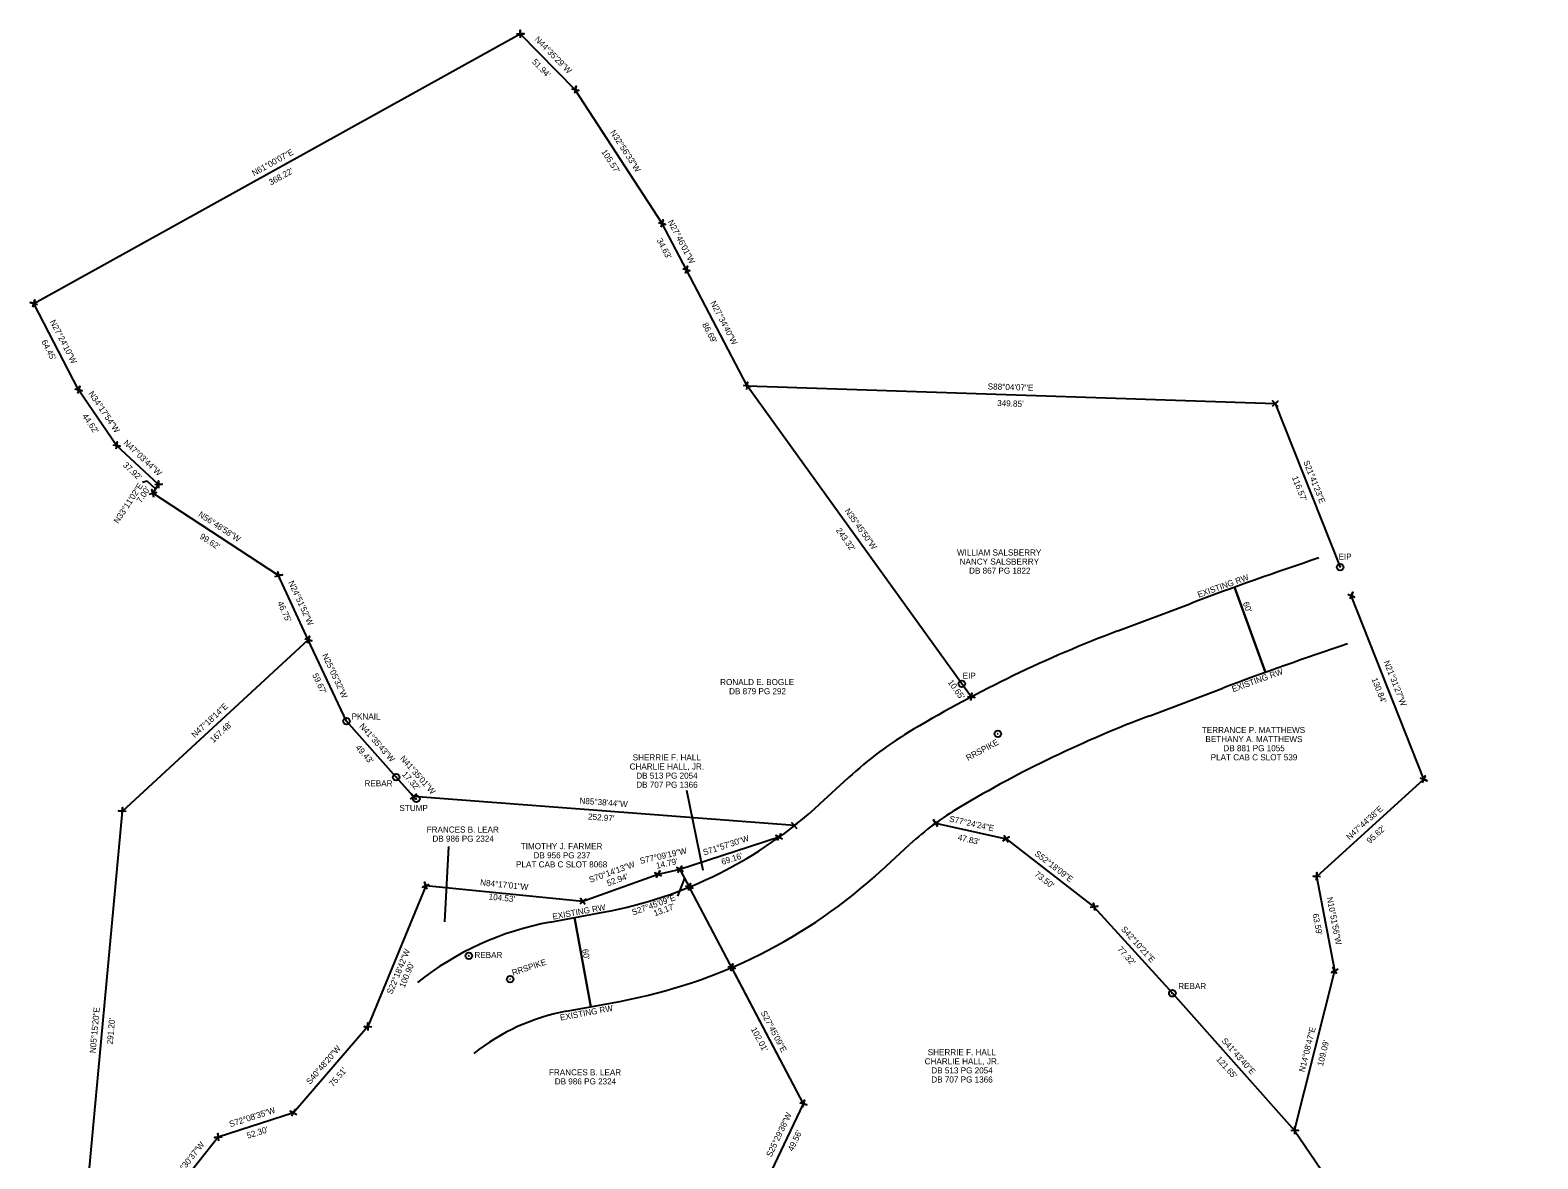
# Model space of a CAD drawing. Extents: x 860808 to 861835, y 630123 to 631311.
# Drawn here: x 860808 to 861806, y 630563 to 631311 of the extents above; entities that cross this region are included whole.
import ezdxf

# ---------------------------------------------------------------- set-up
doc = ezdxf.new("R2010")
doc.units = 0
for name, color, linetype in [('Exist Property Corner CELL', 7, 'Continuous'), ('Exist Property Iron Pin CELL', 7, 'Continuous'), ('Exist Property Line', 7, 'Continuous'), ('Exist Property Text', 7, 'Continuous'), ('Exist Right of Way Line', 7, 'Continuous'), ('Exist Right of Way Text', 7, 'Continuous')]:
    doc.layers.add(name, color=color, linetype=linetype)

msp = doc.modelspace()

# ---------------------------------------------------------------- linework, layer by layer
at = {"layer": 'Exist Property Corner CELL'}
for p, q in [((861132.38, 631308.34), (861132.38, 631308.34)), ((861168.84, 631271.35), (861168.84, 631271.35)), ((861226.25, 631182.75), (861226.25, 631182.75)), ((861242.38, 631152.11), (861242.38, 631152.11)), ((860810.32, 631129.83), (860810.32, 631129.83)), ((860839.98, 631072.61), (860839.98, 631072.61)), ((861282.52, 631075.27), (861282.52, 631075.27)), ((861632.17, 631063.48), (861632.17, 631063.48)), ((860865.13, 631035.75), (860865.13, 631035.75)), ((860889.06, 631004.06), (860889.06, 631004.06)), ((860892.89, 631009.92), (860892.89, 631009.92)), ((860972.43, 630949.54), (860972.43, 630949.54)), ((861682.54, 630936.37), (861682.54, 630936.37)), ((860992.09, 630907.12), (860992.09, 630907.12)), ((861430.95, 630869.19), (861430.95, 630869.19)), ((861730.55, 630814.66), (861730.55, 630814.66)), ((861061.7, 630803.16), (861061.7, 630803.16)), ((860869, 630793.55), (860869, 630793.55)), ((861313.94, 630783.95), (861313.94, 630783.95)), ((861407.39, 630785.59), (861407.39, 630785.59)), ((861303.9, 630776.38), (861303.9, 630776.38)), ((861454.06, 630775.16), (861454.06, 630775.16)), ((861223.71, 630751.67), (861223.71, 630751.67)), ((861238.13, 630754.96), (861238.13, 630754.96)), ((861069.88, 630744.18), (861069.88, 630744.18)), ((861244.27, 630743.31), (861244.27, 630743.31)), ((861659.77, 630750.36), (861659.77, 630750.36)), ((861173.89, 630733.77), (861173.89, 630733.77)), ((861512.22, 630730.22), (861512.22, 630730.22)), ((861272.31, 630690.01), (861272.31, 630690.01)), ((861671.76, 630687.91), (861671.76, 630687.91)), ((861031.58, 630650.84), (861031.58, 630650.84)), ((860982.23, 630593.68), (860982.23, 630593.68)), ((861319.81, 630599.73), (861319.81, 630599.73)), ((861645.1, 630582.13), (861645.1, 630582.13)), ((860932.45, 630577.65), (860932.45, 630577.65))]:
    msp.add_line(p, q, dxfattribs=at)
for points in [[(861129.88, 631308.36), (861134.88, 631308.32), (861132.38, 631308.34), (861132.4, 631310.84), (861132.36, 631305.84)], [(861166.4, 631271.87), (861171.29, 631270.83), (861168.84, 631271.35), (861169.37, 631273.79), (861168.32, 631268.91)], [(861223.86, 631183.5), (861228.64, 631182.01), (861226.25, 631182.75), (861226.99, 631185.14), (861225.51, 631180.37)], [(861240, 631152.86), (861244.77, 631151.36), (861242.38, 631152.11), (861243.13, 631154.5), (861241.64, 631149.73)], [(860809.63, 631127.43), (860811.01, 631132.24), (860810.32, 631129.83), (860807.92, 631130.52), (860812.72, 631129.14)], [(860837.6, 631073.37), (860842.37, 631071.86), (860839.98, 631072.61), (860840.74, 631075), (860839.23, 631070.23)], [(861280.05, 631075.67), (861284.99, 631074.87), (861282.52, 631075.27), (861282.92, 631077.74), (861282.12, 631072.8)], [(861630.34, 631061.77), (861634, 631065.19), (861632.17, 631063.48), (861630.46, 631065.31), (861633.88, 631061.65)], [(860862.67, 631036.22), (860867.58, 631035.29), (860865.13, 631035.75), (860865.59, 631038.21), (860864.66, 631033.3)], [(860890.39, 631009.83), (860895.39, 631010.01), (860892.89, 631009.92), (860892.8, 631012.42), (860892.98, 631007.42)], [(860886.61, 631003.55), (860891.5, 631004.57), (860889.06, 631004.06), (860888.54, 631006.51), (860889.57, 631001.62)], [(860969.98, 630949.03), (860974.88, 630950.05), (860972.43, 630949.54), (860971.92, 630951.99), (860972.94, 630947.09)], [(861680.25, 630937.37), (861684.83, 630935.38), (861682.54, 630936.37), (861683.54, 630938.66), (861681.55, 630934.08)], [(860989.74, 630907.97), (860994.44, 630906.27), (860992.09, 630907.12), (860992.94, 630909.47), (860991.24, 630904.77)], [(861428.48, 630869.59), (861433.42, 630868.79), (861430.95, 630869.19), (861431.35, 630871.66), (861430.55, 630866.72)], [(861728.25, 630815.65), (861732.84, 630813.66), (861730.55, 630814.66), (861731.54, 630816.95), (861729.55, 630812.36)], [(861059.81, 630801.53), (861063.6, 630804.79), (861061.7, 630803.16), (861060.07, 630805.06), (861063.33, 630801.26)], [(860868.89, 630791.05), (860869.1, 630796.05), (860869, 630793.55), (860866.5, 630793.65), (860871.49, 630793.45)], [(861312.04, 630782.33), (861315.84, 630785.58), (861313.94, 630783.95), (861312.31, 630785.85), (861315.57, 630782.06)], [(861405.28, 630784.25), (861409.5, 630786.93), (861407.39, 630785.59), (861406.05, 630787.7), (861408.73, 630783.48)], [(861302.76, 630774.15), (861305.03, 630778.61), (861303.9, 630776.38), (861301.67, 630777.52), (861306.12, 630775.25)], [(861451.95, 630773.82), (861456.18, 630776.5), (861454.06, 630775.16), (861452.73, 630777.27), (861455.4, 630773.05)], [(861222.65, 630749.41), (861224.78, 630753.93), (861223.71, 630751.67), (861221.45, 630752.74), (861225.98, 630750.61)], [(861236.8, 630752.85), (861239.47, 630757.08), (861238.13, 630754.96), (861236.02, 630756.29), (861240.25, 630753.63)], [(861659.65, 630747.86), (861659.89, 630752.85), (861659.77, 630750.36), (861657.28, 630750.48), (861662.27, 630750.24)], [(861070.85, 630741.88), (861068.92, 630746.49), (861069.88, 630744.18), (861067.58, 630743.22), (861072.19, 630745.15)], [(861241.88, 630744.05), (861246.65, 630742.57), (861244.27, 630743.31), (861245.01, 630745.7), (861243.52, 630740.92)], [(861171.96, 630732.19), (861175.83, 630735.35), (861173.89, 630733.77), (861172.31, 630735.71), (861175.48, 630731.84)], [(861509.74, 630729.9), (861514.7, 630730.53), (861512.22, 630730.22), (861511.9, 630732.7), (861512.54, 630727.74)], [(861269.92, 630690.75), (861274.7, 630689.27), (861272.31, 630690.01), (861273.05, 630692.4), (861271.57, 630687.62)], [(861673.04, 630685.76), (861670.48, 630690.05), (861671.76, 630687.91), (861669.61, 630686.63), (861673.91, 630689.19)], [(861031.76, 630648.35), (861031.4, 630653.33), (861031.58, 630650.84), (861029.08, 630650.66), (861034.07, 630651.02)], [(861317.43, 630600.48), (861322.2, 630598.99), (861319.81, 630599.73), (861320.56, 630602.12), (861319.07, 630597.35)], [(860981.09, 630591.46), (860983.37, 630595.91), (860982.23, 630593.68), (860980.01, 630594.83), (860984.46, 630592.54)], [(861642.6, 630582.27), (861647.59, 630581.98), (861645.1, 630582.13), (861645.24, 630584.62), (861644.95, 630579.63)], [(860932.73, 630575.16), (860932.17, 630580.13), (860932.45, 630577.65), (860929.97, 630577.37), (860934.94, 630577.93)]]:
    msp.add_lwpolyline(points, dxfattribs=at)
at = {"layer": 'Exist Property Iron Pin CELL'}
for centre, radius in [((861675.25, 630955.16), 2.2), ((861675.25, 630955.16), 0.0707), ((861424.73, 630877.83), 2.2), ((861424.73, 630877.83), 0.0707), ((861017.39, 630853.08), 2.2), ((861017.39, 630853.08), 0.0707), ((861448.54, 630844.78), 2.2), ((861448.54, 630844.78), 0.0707), ((861050.21, 630816.12), 2.2), ((861050.21, 630816.12), 0.0707), ((861063.62, 630801.67), 2.2), ((861063.62, 630801.67), 0.0707), ((861098.31, 630697.67), 2.2), ((861098.31, 630697.67), 0.0707), ((861125.7, 630682.29), 2.2), ((861125.7, 630682.29), 0.0707), ((861564.13, 630672.91), 2.2), ((861564.13, 630672.91), 0.0707)]:
    msp.add_circle(centre, radius, dxfattribs=at)
at = {"layer": 'Exist Property Line'}
for p, q in [((860810.32, 631129.83), (861132.38, 631308.34)), ((861168.84, 631271.35), (861132.38, 631308.34)), ((861226.25, 631182.75), (861168.84, 631271.35)), ((861242.38, 631152.11), (861226.25, 631182.75)), ((861282.52, 631075.27), (861242.38, 631152.11)), ((860839.98, 631072.61), (860810.32, 631129.83)), ((860865.13, 631035.75), (860839.98, 631072.61)), ((861424.73, 630877.83), (861282.52, 631075.27)), ((861282.52, 631075.27), (861632.17, 631063.48)), ((861632.17, 631063.48), (861675.25, 630955.16)), ((860892.89, 631009.92), (860865.13, 631035.75)), ((860889.06, 631004.06), (860892.89, 631009.92)), ((860972.43, 630949.54), (860889.06, 631004.06)), ((860992.09, 630907.12), (860972.43, 630949.54)), ((861730.55, 630814.66), (861682.54, 630936.37)), ((860869, 630793.55), (860992.09, 630907.12)), ((861017.39, 630853.08), (860992.09, 630907.12)), ((861430.95, 630869.19), (861424.73, 630877.83)), ((861050.21, 630816.12), (861017.39, 630853.08)), ((861061.7, 630803.16), (861050.21, 630816.12)), ((861659.77, 630750.36), (861730.55, 630814.66)), ((861313.94, 630783.95), (861061.7, 630803.16)), ((860842.32, 630503.57), (860869, 630793.55)), ((861407.39, 630785.59), (861454.06, 630775.16)), ((861303.9, 630776.38), (861238.13, 630754.96)), ((861454.06, 630775.16), (861512.22, 630730.22)), ((861223.71, 630751.67), (861173.89, 630733.77)), ((861238.13, 630754.96), (861223.71, 630751.67)), ((861238.13, 630754.96), (861319.81, 630599.73)), ((861238.13, 630754.96), (861244.27, 630743.31)), ((861238.13, 630754.96), (861319.81, 630599.73)), ((861069.88, 630744.18), (861031.58, 630650.84)), ((861173.89, 630733.77), (861069.88, 630744.18)), ((861671.76, 630687.91), (861659.77, 630750.36)), ((861512.22, 630730.22), (861564.13, 630672.91)), ((861272.31, 630690.01), (861319.81, 630599.73)), ((861645.1, 630582.13), (861671.76, 630687.91)), ((861564.13, 630672.91), (861645.1, 630582.13)), ((861031.58, 630650.84), (860982.23, 630593.68)), ((860982.23, 630593.68), (860932.45, 630577.65)), ((861319.81, 630599.73), (861298.48, 630555)), ((861645.1, 630582.13), (861806.12, 630345.46)), ((860932.45, 630577.65), (860901.8, 630539.13))]:
    msp.add_line(p, q, dxfattribs=at)
at = {"layer": 'Exist Property Text'}
for p, q in [((861253.6, 630754.21), (861242.69, 630807.16)), ((861082.44, 630720.21), (861085.18, 630770.07)), ((861241.2, 630749.14), (861236.48, 630737.31))]:
    msp.add_line(p, q, dxfattribs=at)
msp.add_lwpolyline([(860890.97, 631006.99), (860885.3, 631012.12), (860882.36, 631011.26)], dxfattribs=at)
at = {"layer": 'Exist Right of Way Line'}
for p, q in [((861528.04, 630912.91), (861576.28, 630931.11)), ((861549.22, 630856.77), (861597.46, 630874.98)), ((861330.82, 630798.34), (861349.56, 630815.59)), ((861371.46, 630754.2), (861390.19, 630771.45)), ((861152.14, 630720.03), (861187.36, 630726.57)), ((861163.1, 630661.04), (861198.32, 630667.58))]:
    msp.add_line(p, q, dxfattribs=at)
for centre, radius, start, end in [((862382.98, 628793.25), 2285, 108.41329, 110.67352), ((861829.89, 630112.97), 855, 110.67352, 120.7515), ((862382.98, 628793.25), 2225, 108.41329, 110.67352), ((861829.89, 630112.97), 795, 110.67352, 120.7515), ((861525.65, 630624.3), 260, 120.7515, 132.63313), ((861134.4, 631011.69), 290, 280.52274, 312.63313), ((861525.65, 630624.3), 200, 120.7515, 132.63313), ((861134.4, 631011.69), 350, 280.52274, 312.63313), ((861188.67, 630523.39), 200, 100.52274, 128.42782), ((861188.67, 630523.39), 140, 100.52274, 128.42782)]:
    msp.add_arc(centre, radius, start, end, dxfattribs=at)
at = {"layer": 'Exist Right of Way Text'}
for p, q in [((861625.71, 630885.42), (861605.29, 630941.84)), ((861605.29, 630941.84), (861625.71, 630885.42)), ((861179.18, 630664.02), (861168.22, 630723.01)), ((861168.22, 630723.01), (861179.18, 630664.02))]:
    msp.add_line(p, q, dxfattribs=at)

# ---------------------------------------------------------------- texts
at = {"layer": 'Exist Property Text'}
for s, rotation, p in [('N44°35\'29"W', 314.59135, (861141.6, 631304.37)), ("51.94'", 314.59135, (861139.87, 631289.46)), ('N32°56\'33"W', 302.94247, (861191.65, 631243.1)), ('N61°00\'07"E', 28.99802, (860956.1, 631214.06)), ("105.57'", 302.94247, (861185.89, 631230.26)), ("368.22'", 28.99802, (860967.27, 631207.9)), ('N27°46\'01"W', 297.76691, (861229.9, 631183.94)), ("34.63'", 297.76691, (861222.6, 631171.66)), ('N27°34\'40"W', 297.57774, (861258.08, 631130.22)), ('N27°24\'10"W', 297.40274, (860820.83, 631117.76)), ("86.69'", 297.57774, (861252.67, 631115.87)), ("64.45'", 297.40274, (860815.19, 631104.52)), ('N34°17\'54"W', 304.2983, (860846.28, 631070.08)), ('S88°04\'07"E', 358.06854, (861441.83, 631072.9)), ("349.85'", 358.06854, (861448.1, 631061.88)), ("44.62'", 304.2983, (860842.15, 631055.18)), ('N47°03\'44"W', 317.06219, (860869.38, 631036.96)), ("37.92'", 317.06219, (860869, 631022.29)), ('S21°41\'23"E', 291.68971, (861650.73, 631024.94)), ('N33°11\'02"E', 56.81608, (860866.21, 630983.68)), ("116.57'", 291.68971, (861643.22, 631014.6)), ("7.00'", 56.81608, (860881.39, 630997.25)), ('N56°48\'58"W', 326.81608, (860918.86, 630989.09)), ('N35°45\'50"W', 305.76382, (861346.95, 630992.29)), ("243.32'", 305.76382, (861341.2, 630979.46)), ("99.62'", 326.81608, (860919.8, 630974.48)), ('N24°51\'52"W', 294.86449, (860978.68, 630945.04)), ("46.75'", 294.86449, (860971.42, 630931.46)), ('N25°05\'32"W', 295.09229, (861001.09, 630896.8)), ('N21°31\'27"W', 291.52409, (861703.94, 630892.41)), ("59.67'", 295.09229, (860994.58, 630883.79)), ("130.84'", 291.52409, (861695.94, 630880.99)), ("10.65'", 305.76409, (861415.24, 630878.83)), ('N47°18\'14"E', 42.69618, (860916.91, 630841.84)), ("167.48'", 42.69618, (860929.22, 630838.51)), ('N41°35\'43"W', 311.59529, (861025.56, 630849.57)), ('RRSPIKE', 28.57186, (861428.86, 630826.72)), ("49.43'", 311.59529, (861023.05, 630835.37)), ('N41°35\'01"W', 311.58371, (861052.48, 630828.2)), ("17.32'", 311.58371, (861053.85, 630817.7)), ('N85°38\'44"W', 355.64562, (861171.49, 630798.59)), ("252.97'", 355.64562, (861177.17, 630788.05)), ('N47°44\'38"E', 42.25604, (861681.47, 630774.12)), ('S77°24\'24"E', 347.40659, (861416.14, 630786.71)), ("95.62'", 42.25604, (861694.91, 630771.74)), ('S71°57\'30"W', 18.04173, (861254.14, 630764.15)), ("47.83'", 347.40659, (861421.78, 630774.38)), ('S77°09\'19"W', 12.84479, (861212.05, 630758.56)), ("14.79'", 12.84479, (861222.84, 630755.35)), ("69.16'", 18.04173, (861266.27, 630757.86)), ('S52°18\'09"E', 322.30243, (861472.62, 630764.62)), ('S70°14\'13"W', 19.76312, (861178.82, 630746.07)), ("52.94'", 19.76312, (861190.53, 630743.77)), ("73.50'", 322.30243, (861472.5, 630751.06)), ('N84°17\'01"W', 354.28368, (861105.68, 630744.4)), ("104.53'", 354.28368, (861111.32, 630735.02)), ('S27°45\'09"E', 19.74959, (861207.13, 630724.47)), ("13.17'", 20.66782, (861221.58, 630723.81)), ('N10°51\'56"W', 280.86548, (861666.34, 630736.22)), ("63.59'", 280.86548, (861656.91, 630725.34)), ('S42°10\'21"E', 312.1724, (861529.91, 630715.16)), ('S22°18\'42"W', 67.6882, (861047.54, 630671.91)), ("77.32'", 312.1724, (861527.41, 630701.83)), ("100.90'", 67.6882, (861055.81, 630676.25)), ('RRSPIKE', 18.52693, (861127.63, 630684.51)), ('N05°15\'20"E', 84.74451, (860851.23, 630633.13)), ("291.20'", 84.74451, (860862.6, 630638.9)), ('S27°45\'09"E', 297.7526, (861291.44, 630660.09)), ("102.01'", 297.7526, (861284.97, 630649.19)), ('S41°43\'40"E', 311.72773, (861596.46, 630641.17)), ('N14°08\'47"E', 75.85354, (861651.66, 630620.45)), ("109.09'", 75.85354, (861663.8, 630624.39)), ('S40°48\'20"W', 49.19451, (860993.25, 630612.23)), ("75.51'", 49.19451, (861008.43, 630610.67)), ("121.65'", 311.72773, (861592.81, 630629.04)), ('S72°08\'35"W', 17.85701, (860940.46, 630584.2)), ('S25°29\'38"W', 64.50609, (861298.63, 630564.09)), ("52.30'", 17.85701, (860952.07, 630576.56)), ("49.56'", 64.50609, (861312.94, 630567.93)), ('S38°30\'37"W', 51.48979, (860903.89, 630547.82))]:
    msp.add_text(s, height=4.02, rotation=rotation, dxfattribs=at).set_placement(p)
for s, p in [('WILLIAM SALSBERRY', (861421.52, 630962.86)), ('EIP', (861674.16, 630960.08)), ('NANCY SALSBERRY', (861423.29, 630956.83)), ('DB 867 PG 1822', (861429.56, 630950.8)), ('EIP', (861425.32, 630881.32)), ('RONALD E. BOGLE', (861264.75, 630877.03)), ('DB 879 PG 292', (861270.68, 630871)), ('PKNAIL', (861020.75, 630854.23)), ('TERRANCE P. MATTHEWS', (861583.66, 630845.29)), ('BETHANY A. MATTHEWS', (861586.05, 630839.26)), ('DB 881 PG 1055', (861597.93, 630833.23)), ('CHARLIE HALL, JR.', (861204.8, 630821.1)), ('SHERRIE F. HALL', (861206.83, 630827.13)), ('PLAT CAB C SLOT 539', (861589.51, 630827.2)), ('REBAR', (861029.29, 630809.96)), ('DB 707 PG 1366', (861209.2, 630809.04)), ('DB 513 PG 2054', (861209.21, 630815.07)), ('STUMP', (861052.42, 630793.64)), ('FRANCES B. LEAR', (861070.43, 630779.35)), ('DB 986 PG 2324', (861074.27, 630773.32)), ('TIMOTHY J. FARMER', (861132.73, 630768.33)), ('DB 956 PG 237', (861141.19, 630762.3)), ('PLAT CAB C SLOT 8068', (861129.63, 630756.27)), ('REBAR', (861102.07, 630696.31)), ('REBAR', (861568.05, 630675.66)), ('SHERRIE F. HALL', (861402.18, 630631.89)), ('FRANCES B. LEAR', (861151.41, 630618.57)), ('CHARLIE HALL, JR.', (861400.14, 630625.86)), ('DB 513 PG 2054', (861404.56, 630619.83)), ('DB 986 PG 2324', (861155.25, 630612.54)), ('DB 707 PG 1366', (861404.55, 630613.8))]:
    msp.add_text(s, height=4.02, dxfattribs=at).set_placement(p)
at = {"layer": 'Exist Right of Way Text'}
for s, rotation, p in [('EXISTING RW', 19.69005, (861581.63, 630934.87)), ("60'", 289.89781, (861610.75, 630931.38)), ('EXISTING RW', 20.00654, (861604.4, 630872.3)), ('EXISTING RW', 10.52274, (861154.13, 630721.65)), ("60'", 280.52274, (861173.29, 630701.91)), ('EXISTING RW', 10.52274, (861159.11, 630654.77))]:
    msp.add_text(s, height=4.02, rotation=rotation, dxfattribs=at).set_placement(p)

doc.saveas('drawing.dxf')
